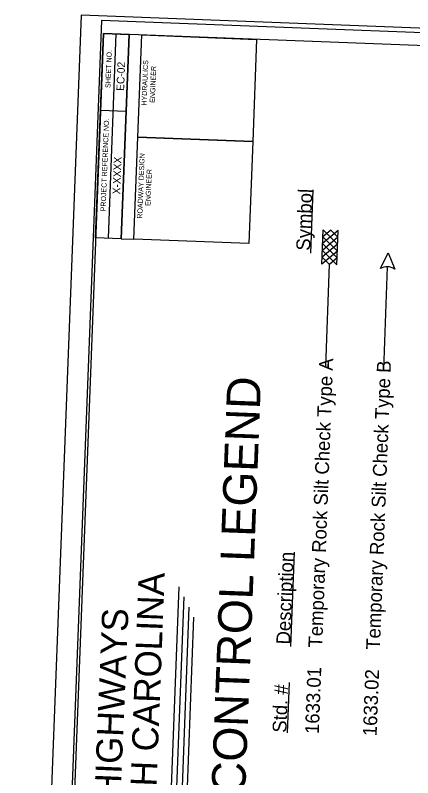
# Model space of a CAD drawing. Extents: x 1654773 to 2116434, y 680831 to 888488.
# Drawn here: x 2109739 to 2111685, y 697117 to 700848 of the extents above; entities that cross this region are included whole.
import ezdxf

# ---------------------------------------------------------------- set-up
doc = ezdxf.new("R2010")
doc.units = 0
for name, color, linetype in [('EC Title Sheet CELL', 7, 'Continuous'), ('Old_Level_1', 7, 'Continuous'), ('Old_Level_12', 7, 'Continuous'), ('Scratch_Level_6', 7, 'Continuous'), ('Sheet Plot Border Inside CELL', 7, 'Continuous'), ('Sheet Plot Border Outside CELL', 7, 'Continuous')]:
    doc.layers.add(name, color=color, linetype=linetype)

msp = doc.modelspace()

# ---------------------------------------------------------------- linework, layer by layer
at = {"layer": 'EC Title Sheet CELL'}
for p, q in [((2111186.5, 699683.1), (2111198.3, 699994.1)), ((2111240.5, 699629.5), (2111246.8, 699798.2)), ((2111283.6, 699796.8), (2111245.5, 699764.2)), ((2111246.8, 699798.2), (2111317.6, 699728.6)), ((2111283.6, 699796.8), (2111319, 699761.4)), ((2111319, 699761.4), (2111242.9, 699696.2)), ((2111320.3, 699795.4), (2111244.4, 699731.4)), ((2111245.5, 699764.2), (2111316.3, 699693.3)), ((2111313.8, 699626.8), (2111320.3, 699795.4)), ((2111317.6, 699728.6), (2111241.8, 699663.4)), ((2111244.4, 699731.4), (2111315.1, 699660.7)), ((2111316.3, 699693.3), (2111240.5, 699629.5)), ((2111242.9, 699696.2), (2111313.8, 699626.8)), ((2111527.6, 699607.9), (2111565.9, 699685)), ((2111565.9, 699685), (2111598, 699605.2)), ((2111241.8, 699663.4), (2111277.2, 699628)), ((2111315.1, 699660.7), (2111277.2, 699628)), ((2111260.7, 699129.8), (2111277.2, 699628)), ((2111543.5, 699114.1), (2111562.4, 699617.1)), ((2111088.8, 697759.8), (2111106.4, 698220.1)), ((2111072.6, 697337.1), (2111081.7, 697582.1))]:
    msp.add_line(p, q, dxfattribs=at)
msp.add_ellipse((2111560.3, 699562.3), major_axis=(59.1, -2.3), ratio=0.927398, start_param=0.944994, end_param=2.196599, dxfattribs=at)
at = {"layer": 'Old_Level_1'}
for p, q in [((2110461.5, 695946), (2110542.3, 698050.4)), ((2110489.1, 695991.1), (2110566.2, 698001.3)), ((2110518, 696036.1), (2110591.5, 697952.1)), ((2110544.2, 696083.4), (2110614.1, 697903))]:
    msp.add_line(p, q, dxfattribs=at)
at = {"layer": 'Scratch_Level_6'}
for p, q in [((2110195.7, 699756.8), (2110234.1, 700756.3)), ((2110258.2, 699754.4), (2110296.5, 700753.9)), ((2110157.2, 700384), (2110282.2, 700379.2)), ((2110339.8, 700251.9), (2110901.6, 700230.3)), ((2110258.2, 699754.4), (2110320.6, 699752))]:
    msp.add_line(p, q, dxfattribs=at)
for points in [[(2110171.4, 700758.7), (2109883.7, 693264.2), (2115129.9, 693062.9), (2115417.5, 700557.4)], [(2110133, 699759.2), (2110171.4, 700758.7), (2110296.5, 700753.9), (2110258.2, 699754.4)], [(2110339.8, 700251.9), (2110359, 700751.5), (2110921.1, 700730), (2110901.9, 700230.3)], [(2110320.6, 699752), (2110339.8, 700251.9), (2110901.9, 700230.3), (2110882.7, 699730.4)]]:
    msp.add_lwpolyline(points, close=True, dxfattribs=at)
at = {"layer": 'Sheet Plot Border Inside CELL'}
msp.add_lwpolyline([(2115112.9, 692295.5), (2115432.4, 700619.3), (2110161.3, 700821.7), (2109841.8, 692497.8)], close=True, dxfattribs=at)
at = {"layer": 'Sheet Plot Border Outside CELL'}
msp.add_lwpolyline([(2115210.4, 692226.7), (2115533.2, 700638), (2110062.2, 700848), (2109739.4, 692436.7)], close=True, dxfattribs=at)

# ---------------------------------------------------------------- texts
at = {"layer": 'EC Title Sheet CELL'}
for s, height, p in [('Symbol', 67.83, (2111182.7, 699695)), ('Temporary Rock Silt Check Type A', 67.828, (2111241.8, 697752.8)), ('Temporary Rock Silt Check Type B', 67.828, (2111524.7, 697741.9)), ('Description', 67.828, (2111084.8, 697767.9)), ('1633.01', 67.74, (2111225.5, 697330.1)), ('1633.02', 67.74, (2111508.4, 697319.2)), ('Std. #', 67.83, (2111066.5, 697336.2))]:
    msp.add_text(s, height=height, rotation=87.802, dxfattribs=at).set_placement(p)
at = {"layer": 'Old_Level_1'}
for s, height, p in [('EROSION & SEDIMENT CONTROL LEGEND', 164.827, (2110769.3, 694549.1)), ('STATE OF NORTH CAROLINA', 128.198, (2110378.7, 695701.8))]:
    msp.add_text(s, height=height, rotation=87.802, dxfattribs=at).set_placement(p)
at = {"layer": 'Old_Level_12'}
msp.add_text(' DIVISION OF HIGHWAYS', height=128.198, rotation=87.5719, dxfattribs=at).set_placement((2110206.5, 695878.5))
at = {"layer": 'Scratch_Level_6'}
for s, height, p in [('SHEET NO.', 25, (2110205.2, 700491.7)), ('EC-02', 37.5, (2110272.1, 700477.2)), ('HYDRAULICS', 25, (2110382.2, 700405.6)), ('ENGINEER', 25, (2110422.5, 700419.1)), ('PROJECT REFERENCE NO.', 25, (2110181.5, 699888.1)), ('X-XXXX', 37.5, (2110253, 699971.2)), ('ROADWAY DESIGN', 25, (2110361, 699852.2)), ('ENGINEER', 25, (2110401.2, 699914.8))]:
    msp.add_text(s, height=height, rotation=87.802, dxfattribs=at).set_placement(p)

doc.saveas('drawing.dxf')
